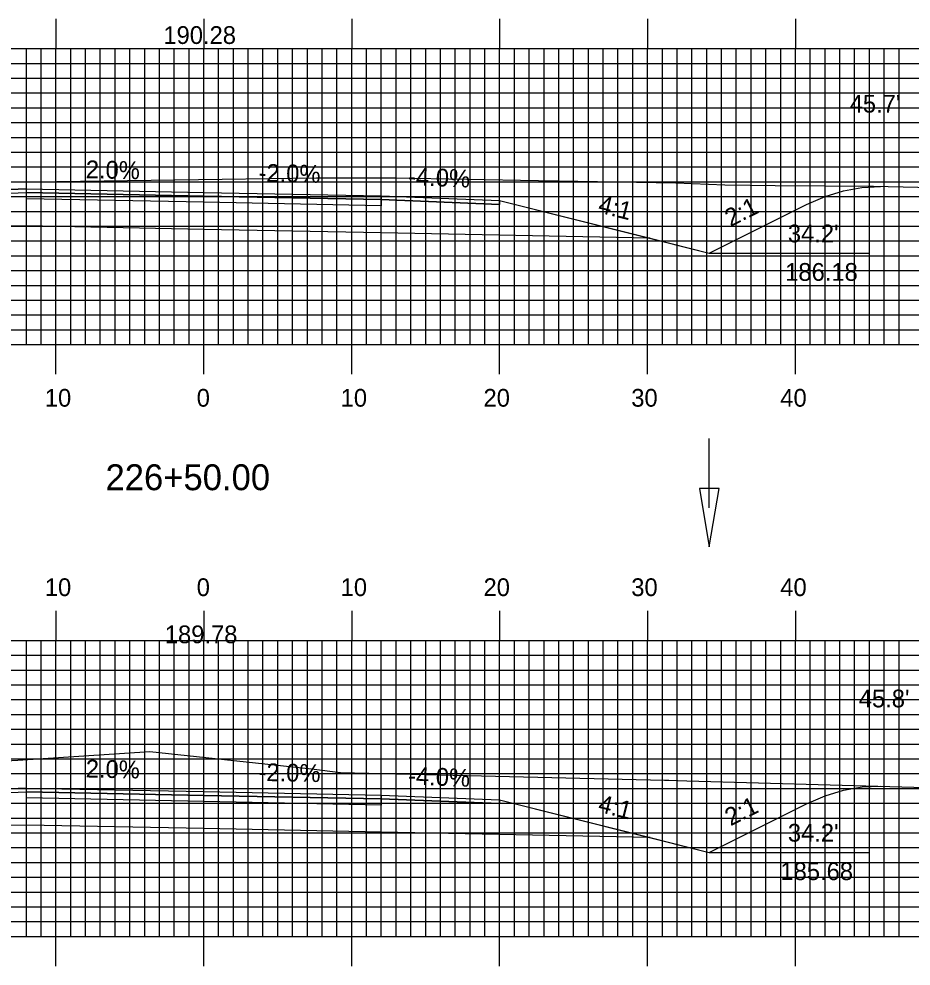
# Model space of a CAD drawing. Extents: x 1798388 to 1798731, y 442591 to 442811.
# Drawn here: x 1798541 to 1798601.3, y 442696.7 to 442760.7 of the extents above; entities that cross this region are included whole.
import ezdxf

# ---------------------------------------------------------------- set-up
doc = ezdxf.new("R2010")
doc.units = 0
for name, color, linetype in [('ANNOTATION', 7, 'Continuous'), ('D_Drainage_Ditch_Line', 7, 'Continuous'), ('D_Roadway_Centerline', 7, 'Continuous'), ('D_Roadway_Centerline_Text', 7, 'Continuous'), ('D_Roadway_Edge_Shoulder', 7, 'Continuous'), ('D_Roadway_Edge_TW', 7, 'Continuous'), ('D_Roadway_Pavement', 7, 'Continuous'), ('D_Roadway_SlopeLines', 7, 'Continuous'), ('D_Roadway_SubGrade', 7, 'Continuous'), ('D_Text_Standard', 7, 'Continuous'), ('H_V ANNOTATION', 7, 'Continuous'), ('MAJOR', 7, 'Continuous'), ('MINOR', 7, 'Continuous'), ('PDRAIN', 7, 'Continuous'), ('S_Roadway_Centerline', 7, 'Continuous')]:
    doc.layers.add(name, color=color, linetype=linetype)

msp = doc.modelspace()

# ---------------------------------------------------------------- linework, layer by layer
at = {"layer": 'D_Drainage_Ditch_Line'}
msp.add_line((1798587.645, 442727.626), (1798587.645, 442732.325), dxfattribs=at)
msp.add_lwpolyline([(1798588.302, 442728.939), (1798586.989, 442728.939), (1798587.645, 442725.002)], close=True, dxfattribs=at)
at = {"layer": 'D_Roadway_Centerline'}
for points in [[(1798507.432, 442750.009), (1798508.682, 442749.93), (1798509.932, 442749.696), (1798511.182, 442749.305), (1798512.432, 442748.758), (1798519.297, 442745.325), (1798523.297, 442746.325), (1798533.471, 442748.869), (1798541.471, 442749.189), (1798553.471, 442748.949), (1798565.471, 442748.709), (1798573.471, 442748.389), (1798583.645, 442745.845), (1798587.645, 442744.845), (1798594.216, 442748.131), (1798595.466, 442748.676), (1798596.716, 442749.061), (1798597.966, 442749.287), (1798599.216, 442749.352)], [(1798505.35, 442710.592), (1798506.6, 442710.495), (1798507.85, 442710.247), (1798509.1, 442709.848), (1798510.35, 442709.299), (1798519.297, 442704.825), (1798523.297, 442705.825), (1798533.471, 442708.369), (1798541.471, 442708.689), (1798553.471, 442708.449), (1798565.471, 442708.209), (1798573.471, 442707.889), (1798583.645, 442705.345), (1798587.645, 442704.345), (1798594.222, 442707.634), (1798595.472, 442708.176), (1798596.722, 442708.553), (1798597.972, 442708.765), (1798599.222, 442708.811)]]:
    msp.add_lwpolyline(points, dxfattribs=at)
at = {"layer": 'D_Roadway_Edge_Shoulder'}
for points in [[(1798541.471, 442749.189), (1798533.471, 442748.869), (1798533.471, 442748.619), (1798541.471, 442748.939)], [(1798565.471, 442748.709), (1798573.471, 442748.389), (1798573.471, 442748.139), (1798565.471, 442748.459)], [(1798541.471, 442708.689), (1798533.471, 442708.369), (1798533.471, 442708.119), (1798541.471, 442708.439)], [(1798565.471, 442708.209), (1798573.471, 442707.889), (1798573.471, 442707.639), (1798565.471, 442707.959)]]:
    msp.add_lwpolyline(points, close=True, dxfattribs=at)
at = {"layer": 'D_Roadway_Edge_TW'}
for points in [[(1798541.471, 442748.939), (1798541.471, 442749.189), (1798553.471, 442748.949), (1798565.471, 442748.709), (1798565.471, 442748.459), (1798553.471, 442748.699)], [(1798541.471, 442708.439), (1798541.471, 442708.689), (1798553.471, 442708.449), (1798565.471, 442708.209), (1798565.471, 442707.959), (1798553.471, 442708.199)]]:
    msp.add_lwpolyline(points, close=True, dxfattribs=at)
at = {"layer": 'D_Roadway_Pavement'}
for points in [[(1798541.471, 442748.522), (1798541.471, 442748.939), (1798553.471, 442748.699), (1798565.471, 442748.459), (1798565.471, 442748.042), (1798553.471, 442748.282)], [(1798541.471, 442708.022), (1798541.471, 442708.439), (1798553.471, 442708.199), (1798565.471, 442707.959), (1798565.471, 442707.542), (1798553.471, 442707.782)]]:
    msp.add_lwpolyline(points, close=True, dxfattribs=at)
at = {"layer": 'D_Roadway_SlopeLines'}
for points in [[(1798587.645, 442744.845), (1798594.216, 442748.131), (1798595.466, 442748.676), (1798596.716, 442749.061), (1798597.966, 442749.287), (1798599.216, 442749.352)], [(1798573.471, 442748.389), (1798587.645, 442744.845)], [(1798587.645, 442704.345), (1798594.222, 442707.634), (1798595.472, 442708.176), (1798596.722, 442708.553), (1798597.972, 442708.765), (1798599.222, 442708.811)], [(1798573.471, 442707.889), (1798587.645, 442704.345)]]:
    msp.add_lwpolyline(points, dxfattribs=at)
at = {"layer": 'D_Roadway_SubGrade'}
for points in [[(1798541.471, 442746.689), (1798523.297, 442746.325), (1798533.471, 442748.869), (1798533.471, 442748.619), (1798541.471, 442748.939), (1798553.471, 442748.699), (1798565.471, 442748.459), (1798573.471, 442748.139), (1798573.471, 442748.389), (1798583.645, 442745.845), (1798565.471, 442746.209), (1798553.471, 442746.449)], [(1798541.471, 442706.189), (1798523.297, 442705.825), (1798533.471, 442708.369), (1798533.471, 442708.119), (1798541.471, 442708.439), (1798553.471, 442708.199), (1798565.471, 442707.959), (1798573.471, 442707.639), (1798573.471, 442707.889), (1798583.645, 442705.345), (1798565.471, 442705.709), (1798553.471, 442705.949)]]:
    msp.add_lwpolyline(points, close=True, dxfattribs=at)
at = {"layer": 'MAJOR'}
for p, q in [((1798543.471, 442760.669), (1798543.471, 442758.665)), ((1798553.471, 442760.669), (1798553.471, 442758.665)), ((1798563.471, 442760.669), (1798563.471, 442758.665)), ((1798573.471, 442760.669), (1798573.471, 442758.665)), ((1798583.471, 442760.669), (1798583.471, 442758.665)), ((1798593.471, 442760.669), (1798593.471, 442758.665)), ((1798413.471, 442758.665), (1798693.471, 442758.665)), ((1798413.471, 442758.665), (1798693.471, 442758.665)), ((1798543.471, 442738.665), (1798543.471, 442758.665)), ((1798553.471, 442738.665), (1798553.471, 442758.665)), ((1798563.471, 442738.665), (1798563.471, 442758.665)), ((1798573.471, 442738.665), (1798573.471, 442758.665)), ((1798583.471, 442738.665), (1798583.471, 442758.665)), ((1798593.471, 442738.665), (1798593.471, 442758.665)), ((1798413.471, 442753.665), (1798693.471, 442753.665)), ((1798413.471, 442748.665), (1798693.471, 442748.665)), ((1798413.471, 442743.665), (1798693.471, 442743.665)), ((1798413.471, 442738.665), (1798693.471, 442738.665)), ((1798413.471, 442738.665), (1798693.471, 442738.665)), ((1798543.471, 442736.661), (1798543.471, 442738.665)), ((1798553.471, 442736.661), (1798553.471, 442738.665)), ((1798563.471, 442736.661), (1798563.471, 442738.665)), ((1798573.471, 442736.661), (1798573.471, 442738.665)), ((1798583.471, 442736.661), (1798583.471, 442738.665)), ((1798593.471, 442736.661), (1798593.471, 442738.665)), ((1798543.471, 442720.669), (1798543.471, 442718.665)), ((1798553.471, 442720.669), (1798553.471, 442718.665)), ((1798563.471, 442720.669), (1798563.471, 442718.665)), ((1798573.471, 442720.669), (1798573.471, 442718.665)), ((1798583.471, 442720.669), (1798583.471, 442718.665)), ((1798593.471, 442720.669), (1798593.471, 442718.665)), ((1798413.471, 442718.665), (1798693.471, 442718.665)), ((1798413.471, 442718.665), (1798693.471, 442718.665)), ((1798543.471, 442698.665), (1798543.471, 442718.665)), ((1798553.471, 442698.665), (1798553.471, 442718.665)), ((1798563.471, 442698.665), (1798563.471, 442718.665)), ((1798573.471, 442698.665), (1798573.471, 442718.665)), ((1798583.471, 442698.665), (1798583.471, 442718.665)), ((1798593.471, 442698.665), (1798593.471, 442718.665)), ((1798413.471, 442713.665), (1798693.471, 442713.665)), ((1798413.471, 442708.665), (1798693.471, 442708.665)), ((1798413.471, 442703.665), (1798693.471, 442703.665)), ((1798413.471, 442698.665), (1798693.471, 442698.665)), ((1798413.471, 442698.665), (1798693.471, 442698.665)), ((1798543.471, 442696.661), (1798543.471, 442698.665)), ((1798553.471, 442696.661), (1798553.471, 442698.665)), ((1798563.471, 442696.661), (1798563.471, 442698.665)), ((1798573.471, 442696.661), (1798573.471, 442698.665)), ((1798583.471, 442696.661), (1798583.471, 442698.665)), ((1798593.471, 442696.661), (1798593.471, 442698.665))]:
    msp.add_line(p, q, dxfattribs=at)
at = {"layer": 'MINOR'}
for p, q in [((1798541.471, 442738.665), (1798541.471, 442758.665)), ((1798542.471, 442738.665), (1798542.471, 442758.665)), ((1798544.471, 442738.665), (1798544.471, 442758.665)), ((1798545.471, 442738.665), (1798545.471, 442758.665)), ((1798546.471, 442738.665), (1798546.471, 442758.665)), ((1798547.471, 442738.665), (1798547.471, 442758.665)), ((1798548.471, 442738.665), (1798548.471, 442758.665)), ((1798549.471, 442738.665), (1798549.471, 442758.665)), ((1798550.471, 442738.665), (1798550.471, 442758.665)), ((1798551.471, 442738.665), (1798551.471, 442758.665)), ((1798552.471, 442738.665), (1798552.471, 442758.665)), ((1798554.471, 442738.665), (1798554.471, 442758.665)), ((1798555.471, 442738.665), (1798555.471, 442758.665)), ((1798556.471, 442738.665), (1798556.471, 442758.665)), ((1798557.471, 442738.665), (1798557.471, 442758.665)), ((1798558.471, 442738.665), (1798558.471, 442758.665)), ((1798559.471, 442738.665), (1798559.471, 442758.665)), ((1798560.471, 442738.665), (1798560.471, 442758.665)), ((1798561.471, 442738.665), (1798561.471, 442758.665)), ((1798562.471, 442738.665), (1798562.471, 442758.665)), ((1798564.471, 442738.665), (1798564.471, 442758.665)), ((1798565.471, 442738.665), (1798565.471, 442758.665)), ((1798566.471, 442738.665), (1798566.471, 442758.665)), ((1798567.471, 442738.665), (1798567.471, 442758.665)), ((1798568.471, 442738.665), (1798568.471, 442758.665)), ((1798569.471, 442738.665), (1798569.471, 442758.665)), ((1798570.471, 442738.665), (1798570.471, 442758.665)), ((1798571.471, 442738.665), (1798571.471, 442758.665)), ((1798572.471, 442738.665), (1798572.471, 442758.665)), ((1798574.471, 442738.665), (1798574.471, 442758.665)), ((1798575.471, 442738.665), (1798575.471, 442758.665)), ((1798576.471, 442738.665), (1798576.471, 442758.665)), ((1798577.471, 442738.665), (1798577.471, 442758.665)), ((1798578.471, 442738.665), (1798578.471, 442758.665)), ((1798579.471, 442738.665), (1798579.471, 442758.665)), ((1798580.471, 442738.665), (1798580.471, 442758.665)), ((1798581.471, 442738.665), (1798581.471, 442758.665)), ((1798582.471, 442738.665), (1798582.471, 442758.665)), ((1798584.471, 442738.665), (1798584.471, 442758.665)), ((1798585.471, 442738.665), (1798585.471, 442758.665)), ((1798586.471, 442738.665), (1798586.471, 442758.665)), ((1798587.471, 442738.665), (1798587.471, 442758.665)), ((1798588.471, 442738.665), (1798588.471, 442758.665)), ((1798589.471, 442738.665), (1798589.471, 442758.665)), ((1798590.471, 442738.665), (1798590.471, 442758.665)), ((1798591.471, 442738.665), (1798591.471, 442758.665)), ((1798592.471, 442738.665), (1798592.471, 442758.665)), ((1798594.471, 442738.665), (1798594.471, 442758.665)), ((1798595.471, 442738.665), (1798595.471, 442758.665)), ((1798596.471, 442738.665), (1798596.471, 442758.665)), ((1798597.471, 442738.665), (1798597.471, 442758.665)), ((1798598.471, 442738.665), (1798598.471, 442758.665)), ((1798599.471, 442738.665), (1798599.471, 442758.665)), ((1798600.471, 442738.665), (1798600.471, 442758.665)), ((1798413.471, 442757.665), (1798693.471, 442757.665)), ((1798413.471, 442756.665), (1798693.471, 442756.665)), ((1798413.471, 442755.665), (1798693.471, 442755.665)), ((1798413.471, 442754.665), (1798693.471, 442754.665)), ((1798413.471, 442752.665), (1798693.471, 442752.665)), ((1798413.471, 442751.665), (1798693.471, 442751.665)), ((1798413.471, 442750.665), (1798693.471, 442750.665)), ((1798413.471, 442749.665), (1798693.471, 442749.665)), ((1798413.471, 442747.665), (1798693.471, 442747.665)), ((1798413.471, 442746.665), (1798693.471, 442746.665)), ((1798413.471, 442745.665), (1798693.471, 442745.665)), ((1798413.471, 442744.665), (1798693.471, 442744.665)), ((1798413.471, 442742.665), (1798693.471, 442742.665)), ((1798413.471, 442741.665), (1798693.471, 442741.665)), ((1798413.471, 442740.665), (1798693.471, 442740.665)), ((1798413.471, 442739.665), (1798693.471, 442739.665)), ((1798541.471, 442698.665), (1798541.471, 442718.665)), ((1798542.471, 442698.665), (1798542.471, 442718.665)), ((1798544.471, 442698.665), (1798544.471, 442718.665)), ((1798545.471, 442698.665), (1798545.471, 442718.665)), ((1798546.471, 442698.665), (1798546.471, 442718.665)), ((1798547.471, 442698.665), (1798547.471, 442718.665)), ((1798548.471, 442698.665), (1798548.471, 442718.665)), ((1798549.471, 442698.665), (1798549.471, 442718.665)), ((1798550.471, 442698.665), (1798550.471, 442718.665)), ((1798551.471, 442698.665), (1798551.471, 442718.665)), ((1798552.471, 442698.665), (1798552.471, 442718.665)), ((1798554.471, 442698.665), (1798554.471, 442718.665)), ((1798555.471, 442698.665), (1798555.471, 442718.665)), ((1798556.471, 442698.665), (1798556.471, 442718.665)), ((1798557.471, 442698.665), (1798557.471, 442718.665)), ((1798558.471, 442698.665), (1798558.471, 442718.665)), ((1798559.471, 442698.665), (1798559.471, 442718.665)), ((1798560.471, 442698.665), (1798560.471, 442718.665)), ((1798561.471, 442698.665), (1798561.471, 442718.665)), ((1798562.471, 442698.665), (1798562.471, 442718.665)), ((1798564.471, 442698.665), (1798564.471, 442718.665)), ((1798565.471, 442698.665), (1798565.471, 442718.665)), ((1798566.471, 442698.665), (1798566.471, 442718.665)), ((1798567.471, 442698.665), (1798567.471, 442718.665)), ((1798568.471, 442698.665), (1798568.471, 442718.665)), ((1798569.471, 442698.665), (1798569.471, 442718.665)), ((1798570.471, 442698.665), (1798570.471, 442718.665)), ((1798571.471, 442698.665), (1798571.471, 442718.665)), ((1798572.471, 442698.665), (1798572.471, 442718.665)), ((1798574.471, 442698.665), (1798574.471, 442718.665)), ((1798575.471, 442698.665), (1798575.471, 442718.665)), ((1798576.471, 442698.665), (1798576.471, 442718.665)), ((1798577.471, 442698.665), (1798577.471, 442718.665)), ((1798578.471, 442698.665), (1798578.471, 442718.665)), ((1798579.471, 442698.665), (1798579.471, 442718.665)), ((1798580.471, 442698.665), (1798580.471, 442718.665)), ((1798581.471, 442698.665), (1798581.471, 442718.665)), ((1798582.471, 442698.665), (1798582.471, 442718.665)), ((1798584.471, 442698.665), (1798584.471, 442718.665)), ((1798585.471, 442698.665), (1798585.471, 442718.665)), ((1798586.471, 442698.665), (1798586.471, 442718.665)), ((1798587.471, 442698.665), (1798587.471, 442718.665)), ((1798588.471, 442698.665), (1798588.471, 442718.665)), ((1798589.471, 442698.665), (1798589.471, 442718.665)), ((1798590.471, 442698.665), (1798590.471, 442718.665)), ((1798591.471, 442698.665), (1798591.471, 442718.665)), ((1798592.471, 442698.665), (1798592.471, 442718.665)), ((1798594.471, 442698.665), (1798594.471, 442718.665)), ((1798595.471, 442698.665), (1798595.471, 442718.665)), ((1798596.471, 442698.665), (1798596.471, 442718.665)), ((1798597.471, 442698.665), (1798597.471, 442718.665)), ((1798598.471, 442698.665), (1798598.471, 442718.665)), ((1798599.471, 442698.665), (1798599.471, 442718.665)), ((1798600.471, 442698.665), (1798600.471, 442718.665)), ((1798413.471, 442717.665), (1798693.471, 442717.665)), ((1798413.471, 442716.665), (1798693.471, 442716.665)), ((1798413.471, 442715.665), (1798693.471, 442715.665)), ((1798413.471, 442714.665), (1798693.471, 442714.665)), ((1798413.471, 442712.665), (1798693.471, 442712.665)), ((1798413.471, 442711.665), (1798693.471, 442711.665)), ((1798413.471, 442710.665), (1798693.471, 442710.665)), ((1798413.471, 442709.665), (1798693.471, 442709.665)), ((1798413.471, 442707.665), (1798693.471, 442707.665)), ((1798413.471, 442706.665), (1798693.471, 442706.665)), ((1798413.471, 442705.665), (1798693.471, 442705.665)), ((1798413.471, 442704.665), (1798693.471, 442704.665)), ((1798413.471, 442702.665), (1798693.471, 442702.665)), ((1798413.471, 442701.665), (1798693.471, 442701.665)), ((1798413.471, 442700.665), (1798693.471, 442700.665)), ((1798413.471, 442699.665), (1798693.471, 442699.665))]:
    msp.add_line(p, q, dxfattribs=at)
at = {"layer": 'PDRAIN'}
for p, q in [((1798587.645, 442744.845), (1798598.416, 442744.845)), ((1798587.645, 442704.345), (1798598.416, 442704.345))]:
    msp.add_line(p, q, dxfattribs=at)
at = {"layer": 'S_Roadway_Centerline'}
for points in [[(1798474.572, 442750.35), (1798495.745, 442750.413), (1798498.22, 442750.306), (1798502.827, 442750.011), (1798516.971, 442750.005), (1798518.506, 442749.989), (1798519.037, 442749.991), (1798524.492, 442749.906), (1798540.357, 442749.649), (1798541.944, 442749.661), (1798561.083, 442749.923), (1798566.412, 442749.934), (1798576.086, 442749.745), (1798585.386, 442749.59), (1798588.692, 442749.454), (1798592.089, 442749.422), (1798598.752, 442749.363), (1798605.74, 442749.203)], [(1798491.776, 442710.895), (1798496.884, 442710.737), (1798510.184, 442710.509), (1798519.231, 442710.544), (1798534.939, 442710.23), (1798540.89, 442710.575), (1798549.829, 442711.165), (1798560.753, 442709.983), (1798562.71, 442709.733), (1798584.609, 442709.231), (1798584.906, 442709.222), (1798586.136, 442709.189), (1798605.514, 442708.63)]]:
    msp.add_lwpolyline(points, dxfattribs=at)

# ---------------------------------------------------------------- texts
at = {"layer": 'ANNOTATION'}
for s, rotation, p in [('2.0%', 358.85424, (1798545.478, 442749.909)), ('-2.0%', 358.85424, (1798557.157, 442749.675)), ('-4.0%', 357.70939, (1798567.262, 442749.439)), ('4:1', 345.96376, (1798580.064, 442747.602)), ('2:1', 26.56505, (1798589.076, 442746.597)), ('2.0%', 358.85424, (1798545.478, 442709.409)), ('-2.0%', 358.85424, (1798557.157, 442709.175)), ('-4.0%', 357.70939, (1798567.262, 442708.939)), ('4:1', 345.96376, (1798580.064, 442707.102)), ('2:1', 26.56505, (1798589.078, 442706.098))]:
    msp.add_text(s, height=1.2, rotation=rotation, dxfattribs=at).set_placement(p)
for s, p in [("34.2'", (1798592.955, 442745.571)), ('186.18', (1798592.773, 442742.971)), ("34.2'", (1798592.955, 442705.071)), ('185.68', (1798592.452, 442702.471))]:
    msp.add_text(s, height=1.2, dxfattribs=at).set_placement(p)
at = {"layer": 'D_Roadway_Centerline'}
for s, p in [('C', (1798553.465, 442748.949)), ('L', (1798553.471, 442748.941)), ('C', (1798553.465, 442708.449)), ('L', (1798553.471, 442708.441))]:
    msp.add_text(s, height=0.0146, dxfattribs=at).set_placement(p)
at = {"layer": 'D_Roadway_Centerline_Text'}
for s, p in [('190.28', (1798550.736, 442758.979)), ('189.78', (1798550.833, 442718.479))]:
    msp.add_text(s, height=1.2, dxfattribs=at).set_placement(p)
at = {"layer": 'D_Text_Standard'}
for s, p in [("45.7'", (1798597.135, 442754.34)), ("45.8'", (1798597.749, 442714.144))]:
    msp.add_text(s, height=1.2, dxfattribs=at).set_placement(p)
at = {"layer": 'H_V ANNOTATION'}
for s, height, p in [('10', 1.2, (1798542.721, 442734.465)), ('0', 1.2, (1798552.989, 442734.465)), ('10', 1.2, (1798562.721, 442734.465)), ('20', 1.2, (1798572.379, 442734.465)), ('30', 1.2, (1798582.368, 442734.465)), ('40', 1.2, (1798592.443, 442734.465)), ('226+50.00', 1.75, (1798546.822, 442728.821)), ('10', 1.2, (1798542.721, 442721.665)), ('0', 1.2, (1798552.989, 442721.665)), ('10', 1.2, (1798562.721, 442721.665)), ('20', 1.2, (1798572.379, 442721.665)), ('30', 1.2, (1798582.368, 442721.665)), ('40', 1.2, (1798592.443, 442721.665))]:
    msp.add_text(s, height=height, dxfattribs=at).set_placement(p)

doc.saveas('drawing.dxf')
